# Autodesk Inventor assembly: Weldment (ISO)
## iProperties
Length Units: 11269
Angle Units: 11283
Time Units: 11279
Mass Units: 11290
Length Display Precision: 3
Angle Display Precision: 2
Part Number: Weldment (ISO)
Document SubType Name: Weldment
Created: 2002-06
Designer: smithga
Part Number: Ens_reduction_V3
Created: 2008-04
Designer: plup
Material: Aluminum soudé-6061
Control State: 0
Master: False
Shininess: 64.0
Angle Units: 11279
Time Units: 11290
Mass Units: 11283
Compacted: True
Density: 0.0
Volumn: 0.0
Area: 0.0
PropertySet Name: Model Information
Author: plup
